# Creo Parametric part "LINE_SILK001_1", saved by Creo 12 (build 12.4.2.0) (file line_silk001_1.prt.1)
Units: Custom; MM, KILOGRAM, SECS

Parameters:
  PTC_WM_ITERATION = "0"
  PTC_WM_VERSION = "-.0"
  PTC_WM_LIFECYCLE_STATE = "In Work"
  PTC_WM_LIFECYCLE = "MO_CADDocument"
  PTC_WM_CREATED_BY = "Maximilian Roepper (Z0017RMS: MO)"
  PTC_WM_CREATED_ON = "18-Sep-26 11:36:42 AM"
  PTC_WM_MODIFIED_BY = "Maximilian Roepper (Z0017RMS: MO)"
  PTC_WM_MODIFIED_ON = "18-Sep-26 11:36:46 AM"
  PDMLINKNUMBER = "PDM000071454937"
  PTC_WM_NAME = "line_silk001_1.prt"
  PTC_WM_NUMBER = "PDM000071454937"

Other parameters: WEIGHT, WEIGHT_FACTOR, WEIGHT_ADD, _MASS_TEMP, _DIFF_TEMP, MC_ERRORS, SUPPLIER

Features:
  1. coordinate system
  2. datum plane "PRT_YZ"
  3. datum plane "PRT_XY"
  4. datum plane "PRT_XZ"
  5. coordinate system
  6. datum axis
  7. datum axis
  8. datum axis
  9. coordinate system
  10. imported feature

Other named items: PRT, SIEMENS_MO, DRW_VIEW_ORG, PRT_X, PRT_Y, PRT_Z, CS0, ROUGH_GROB

Layers: 00_STD_CSYS-KSYS, 01_STD_PLANES-EBENEN, 02_STD_AXES-ACHSEN, 03_STD_CSYS-KSYS, 24_IMPORT_FEAT-IMPORT_KE

Surfaces: 8 plane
